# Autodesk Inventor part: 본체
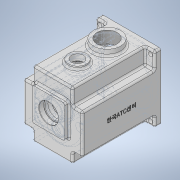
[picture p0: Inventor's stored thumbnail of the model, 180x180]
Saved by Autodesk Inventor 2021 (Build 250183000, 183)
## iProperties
Created: 2022-08
Part Number: 본체
Material: 일반
Document SubType Name: Modeling
Designer: Owner
Density: 1 g/cm^3
Appearance: 기본값
Mass: 520.076 g
Surface Area: 1170.75 cm^2
Volume: 520.076 cm^3
Author: Owner
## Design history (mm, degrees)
sketch "스케치2"
  geometry: L1 (-55, 49)-(55, 49); L2 (55, 49)-(55, -49); L3 (55, -49)-(-55, -49); L4 (-55, -49)-(-55, 49); L5 (-55, 49)-(55, -49); L6 (55, 49)-(-55, -49); 1 further point
  constraints: 12 end point, 2 midpoint, 2 parallel, 1 horizontal, 1 perpendicular
  dimensions: "d0" = 110 distance between parallel lines of L4 L2; "d1" = 98 distance between parallel lines of L3 L1
extrude "돌출1" new body sketch "스케치2" distance "d2" = 130; taper "d3" = 0 deg
sketch "스케치3"
  geometry: L1 (33, 55)-(49, 55); L2 (49, 55)-(49, 28); L3 (49, 28)-(33, 28); L4 (33, 28)-(33, 55); L5 (49, 55)-(-49, 55) reference; L6 (49, -55)-(49, 55) reference; 1 further point
  constraints: 8 end point, 2 parallel, 1 horizontal, 1 perpendicular
  dimensions: "d4" = 27 distance between parallel lines of L3 L1; "d5" = 16 distance between parallel lines of L2 L4; "d6" = 0 distance between parallel lines of L5 L1; "d7" = 0 distance between parallel lines of L6 L2
extrude "돌출2" cut sketch "스케치3" distance "d8" = 120; taper "d9" = 0 deg
node "작업 평면1"
sketch "스케치4"
  geometry: L1 (33, -38)-(49, -38); L2 (49, -38)-(49, -55); L3 (49, -55)-(33, -55); L4 (33, -55)-(33, -38); L5 (-49, -55)-(49, -55) reference; L6 (49, -55)-(49, 28) reference; 1 further point
  constraints: 8 end point, 2 parallel, 1 horizontal, 1 perpendicular
  dimensions: "d11" = 17 distance between parallel lines of L1 L3; "d12" = 16 distance between parallel lines of L2 L4; "d13" = 0 distance between parallel lines of L5 L3; "d14" = 0 distance between parallel lines of L6 L2
extrude "돌출3" cut sketch "스케치4" distance "d15" = 120; taper "d16" = 0 deg
sketch "스케치5"
  geometry: L1 (-23, 45)-(23, 45); L2 (23, 45)-(23, 33.249); L3 (-23, 33.249)-(-23, 45); L4 (-49, -55)-(49, -55) reference; A1 r 42 centre (0, -5) between (-25.375, 28.468) and (25.375, 28.468); A2 r 6 centre (-29, 33.249) between (-25.375, 28.468) and (-23, 33.249); A3 r 6 centre (29, 33.249) between (23, 33.249) and (25.375, 28.468); 5 further points
  constraints: 8 point on circle, 6 end point, 4 tangent, 3 centre point, 2 point on line, 1 horizontal, 1 parallel, 1 perpendicular, 1 vertical alignment
  dimensions: "d18" = 84 diameter of A1; "d19" = 50 distance from line of L4 A1.centre; "d20" = 50 distance from line of A1.centre L1; "d21" = 46 distance between parallel lines of L2 L3; "d22" = 23 distance from line of point (0, 0) L2; "d28" = 6 radius of A2; "d29" = 6 radius of A3
extrude "돌출4" cut sketch "스케치5" distance "d23" = 121; taper "d24" = 0 deg
sketch "스케치7"
  geometry: L1 (23, 45)-(23, 33.249) reference; L2 (-23, 45)-(23, 45) reference; L3 (-23, 33.249)-(-23, 45) reference; L4 (26, 48)-(26, 33.249); L5 (-26, 33.249)-(-26, 48); L6 (-26, 48)-(26, 48); A1 r 6 centre (29, 33.249) between (23, 33.249) and (25.375, 28.468) reference; A2 r 6 centre (-29, 33.249) between (-25.375, 28.468) and (-23, 33.249) reference; A3 r 42 centre (0, -5) between (-25.375, 28.468) and (25.375, 28.468) reference; A4 r 3 centre (29, 33.249) between (26, 33.249) and (27.188, 30.859); A5 r 45 centre (0, -5) between (-27.188, 30.859) and (27.188, 30.859); A6 r 3 centre (-29, 33.249) between (-27.188, 30.859) and (-26, 33.249); 1 further point
  constraints: 6 end point, 6 point on circle, 3 centre point, 5 other
  dimensions: "d30" = 3 distance between parallel lines of L2 L6
extrude "돌출6" cut sketch "스케치7" distance "d31" = 9; taper "d32" = 0 deg
sketch "스케치8"
  geometry: L1 (0, 98)-(0, 0) reference; C1 r 22.5 at (-40, 49); 2 further points
  constraints: 1 centre point, 1 horizontal alignment, 1 midpoint
  dimensions: "d33" = 40 distance from line of L1 C1.centre; "d34" = 45 diameter of C1
extrude "돌출7" join sketch "스케치8" distance "d35" = 10; taper "d36" = 0 deg
sketch "스케치9"
  geometry: C1 r 22.5 at (0, 0) reference; 2 further points
  constraints: 1 coincident
hole "구멍1" sketch "스케치9" at (0, 0) diameter "d37" = 33.376; stored, may be unused: countersink angle "d41" = 90 deg, drill point angle "d43" = 118 deg; dims "d38" = 70, "d39" = 4, "d40" = 2, "d42" = 77.3
sketch "스케치10"
  geometry: L1 (0, 98)-(0, 0) reference; C1 r 15 at (-89, 49); 2 further points
  constraints: 1 centre point, 1 horizontal alignment, 1 midpoint
  dimensions: "d44" = 30 diameter of C1; "d45" = 89 distance from line of L1 C1.centre
extrude "돌출8" join sketch "스케치10" distance "d46" = 5; taper "d47" = 0 deg
sketch "스케치11"
  geometry: C1 r 15 at (0, 0) reference; C2 r 15 at (0, 0) reference; C3 r 10 at (0, 0); 1 further point
  constraints: 1 centre point, 1 coincident
  dimensions: "d48" = 20 diameter of C3
extrude "돌출9" cut sketch "스케치11" distance "d49" = 37.5; taper "d50" = 0 deg
sketch "스케치12"
  geometry: C1 r 10 at (32, 23) reference; C2 r 15 at (32, 23); 1 further point
  constraints: 1 centre point, 1 coincident
  dimensions: "d51" = 30 diameter of C2
extrude "돌출10" cut sketch "스케치12" distance "d52" = 5; taper "d53" = 0 deg
sketch "스케치13"
  geometry: L1 (-27, -21)-(27, -21); L2 (27, -21)-(27, 33); L3 (27, 33)-(-27, 33); L4 (-27, 33)-(-27, -21); L5 (-27, -21)-(27, 33); L6 (27, -21)-(-27, 33); L7 (49, 28)-(33, 28) reference; L8 (-33, -55)-(33, -55) reference; 3 further points
  constraints: 12 end point, 3 midpoint, 2 parallel, 1 horizontal, 1 perpendicular, 1 vertical alignment
  dimensions: "d54" = 54 distance between parallel lines of L2 L4; "d55" = 54 distance between parallel lines of L3 L1; "d73" = 88 distance between parallel lines of L3 L8
extrude "돌출11" join sketch "스케치13" distance "d56" = 7; taper "d57" = 0 deg
sketch "스케치23" dims "d83" = 8
  geometry: L1 (-71.164, -5)-(75.838, -5); L2 (-49, -55)-(49, -55) reference; L3 (-35.778, -1.006)-(-41.81, -1.006); L4 (-35.778, -8.994)-(-41.81, -8.994); A1 r 36 centre (0, -5) between (-36, -5) and (-35.778, -1.006); A2 r 42 centre (0, -5) between (-25.375, 28.468) and (25.375, 28.468) reference; 3 further points
  constraints: 6 end point, 3 point on circle, 2 horizontal, 2 symmetric about line, 1 centre point, 1 point on line, 1 vertical alignment, 3 other
  dimensions: "d82" = 50 distance between parallel lines of L2 L1; "d84" = 72 diameter of A1; "d85" = 50 distance from line of L2 A1.centre
extrude "돌출12" join sketch "스케치23" stored distance "d86" = 7; taper "d87" = 0 deg
sketch "스케치26"
  geometry: L1 (33, -55)-(-33, -55) reference; C1 r 21 at (0, 6); C2 r 15 at (0, -25); 3 further points
  constraints: 2 centre point, 2 vertical alignment
  dimensions: "d88" = 42 diameter of C1; "d89" = 61 distance from line of L1 C1.centre; "d90" = 31 distance of C1.centre C2.centre; "d91" = 30 diameter of C2
extrude "돌출13" join sketch "스케치26" distance "d92" = 7; taper "d93" = 0 deg
sketch "스케치27"
  geometry: C1 r 11 at (0, -25); A1 r 15 centre (0, -25) between (-8.978, -12.984) and (8.978, -12.984) reference; 1 further point
  constraints: 1 centre point, 1 coincident
  dimensions: "d94" = 22 diameter of C1
extrude "돌출14" cut sketch "스케치27" distance "d95" = 7; taper "d96" = 0 deg
sketch "스케치28"
  geometry: C1 r 11 at (0, 0) reference; C2 r 9.5 at (0, 0); 1 further point
  constraints: 1 centre point, 1 coincident
  dimensions: "d97" = 19 diameter of C2
extrude "돌출15" cut sketch "스케치28" distance "d98" = 3; taper "d99" = 0 deg
sketch "스케치29"
  geometry: C1 r 17.5 at (0, 6); A1 r 21 centre (0, 6) between (8.978, -12.984) and (-8.978, -12.984) reference; 1 further point
  constraints: 1 centre point, 1 coincident
  dimensions: "d100" = 35 diameter of C1
extrude "돌출16" cut sketch "스케치29" distance "d101" = 10; taper "d102" = 0 deg
sketch "스케치30"
  geometry: C1 r 17.5 at (0, 0) reference; C2 r 14 at (0, 0); 1 further point
  constraints: 1 centre point, 1 coincident
  dimensions: "d103" = 28 diameter of C2
extrude "돌출17" cut sketch "스케치30" stored distance "d104" = 10; taper "d105" = 0 deg
sketch "스케치31"
  geometry: C1 r 14 at (0, 6) reference; C2 r 16 at (0, 6); A1 r 21 centre (0, 6) between (8.978, -12.984) and (-8.978, -12.984) reference; 1 further point
  constraints: 1 centre point, 1 coincident
  dimensions: "d106" = 32 diameter of C2
extrude "돌출18" cut sketch "스케치31" distance "d107" = 8.3; taper "d108" = 0 deg
sketch "스케치32"
  geometry: L1 (-49, 55)-(-49, -55) reference; L2 (49, 55)-(-49, 55) reference; C1 r 3.5 at (-42, 48); 1 further point
  constraints: 1 centre point
  dimensions: "d109" = 7 diameter of C1; "d110" = 7 distance from line of L1 C1.centre; "d111" = 7 distance from line of L2 C1.centre
extrude "돌출19" cut sketch "스케치32" stored distance "d112" = 8.3; taper "d113" = 0 deg
sketch "스케치33"
  geometry: A1 r 4 centre (-36, -5) between (-35.778, -8.994) and (-35.778, -1.006) reference; 2 further points
  constraints: 1 coincident
hole "구멍2" sketch "스케치33" at (-36, -5) diameter "d120" = 3.242; stored, may be unused: countersink angle "d124" = 90 deg, drill point angle "d126" = 118 deg; dims "d121" = 7, "d122" = 4, "d123" = 2, "d125" = 9
sketch "스케치34"
  geometry: A1 r 4 centre (36, -5) between (35.778, -1.006) and (35.778, -8.994) reference; 2 further points
  constraints: 1 coincident
hole "구멍3" sketch "스케치34" at (36, -5) diameter "d127" = 3.242; stored, may be unused: countersink angle "d131" = 90 deg, drill point angle "d133" = 118 deg; dims "d128" = 7, "d129" = 4, "d130" = 2, "d132" = 9
sketch "스케치35"
  geometry: L1 (-130, 17)-(-130, 83) reference; L2 (-130, 110)-(-10, 110) reference; 2 further points
  constraints: 1 other
  dimensions: "d134" = 65 distance from line of L1 point (-65, 50); "d135" = 60 distance from line of L2 point (-65, 50)
feature "엠보싱1" sketch "스케치35" dims "d136" = 0.5, "d137" = 0
fillet "모깎기1" dims "d141" = 3
fillet "모깎기3" dims "d143" = 6
chamfer "모따기2" distance "d144" = 1; stored, may be unused: second distance "d145" = 2, angle "d146" = 45 deg
fillet "모깎기5" dims "d148" = 3
fillet "모깎기6" dims "d149" = 3
fillet "모깎기7" dims "d150" = 3
fillet "모깎기8" dims "d151" = 3
fillet "모깎기9" dims "d152" = 0.3
fillet "모깎기10" dims "d153" = 0.3
fillet "모깎기11" dims "d154" = 0.3
chamfer "모따기3" distance "d155" = 0.8; stored, may be unused: second distance "d156" = 2, angle "d157" = 30 deg
chamfer "모따기4" distance "d158" = 1; stored, may be unused: second distance "d159" = 2, angle "d160" = 30 deg
fillet "모깎기15" dims "d164" = 3
fillet "모깎기18" dims "d167" = 3
fillet "모깎기19" dims "d168" = 3
fillet "모깎기20" dims "d169" = 3
fillet "모깎기21" dims "d170" = 3
fillet "모깎기22" dims "d171" = 3
fillet "모깎기23" dims "d172" = 3
fillet "모깎기24" dims "d173" = 3
fillet "모깎기25" dims "d174" = 3
fillet "모깎기26" dims "d175" = 3
fillet "모깎기27" dims "d176" = 3
fillet "모깎기28" dims "d177" = 3
fillet "모깎기29" dims "d178" = 3
fillet "모깎기30" dims "d179" = 3
fillet "모깎기31" dims "d180" = 3
fillet "모깎기32" dims "d181" = 3
fillet "모깎기33" dims "d182" = 3
chamfer "모따기5" distance "d183" = 1; stored, may be unused: second distance "d184" = 2, angle "d185" = 30 deg
fillet "모깎기34" dims "d186" = 3
fillet "모깎기35" dims "d187" = 3
node "솔리드1"
mirror "미러1"
mirror "미러2"
mirror "미러3"
pattern_linear "직사각형 패턴1" dims "d116" = 84, "d119" = 96
node "투영된 루프2"
node "투영된 루프3"
feature "A9D066F2-1C7D-4E18-AEED-F7BC21143FA4" dims "d37" = 33.376, "d38" = 70, "d39" = 4, "d40" = 2, "d41" = 90 deg, "d42" = 77.3, "d43" = 118 deg
other parameters: "d10" = -49
